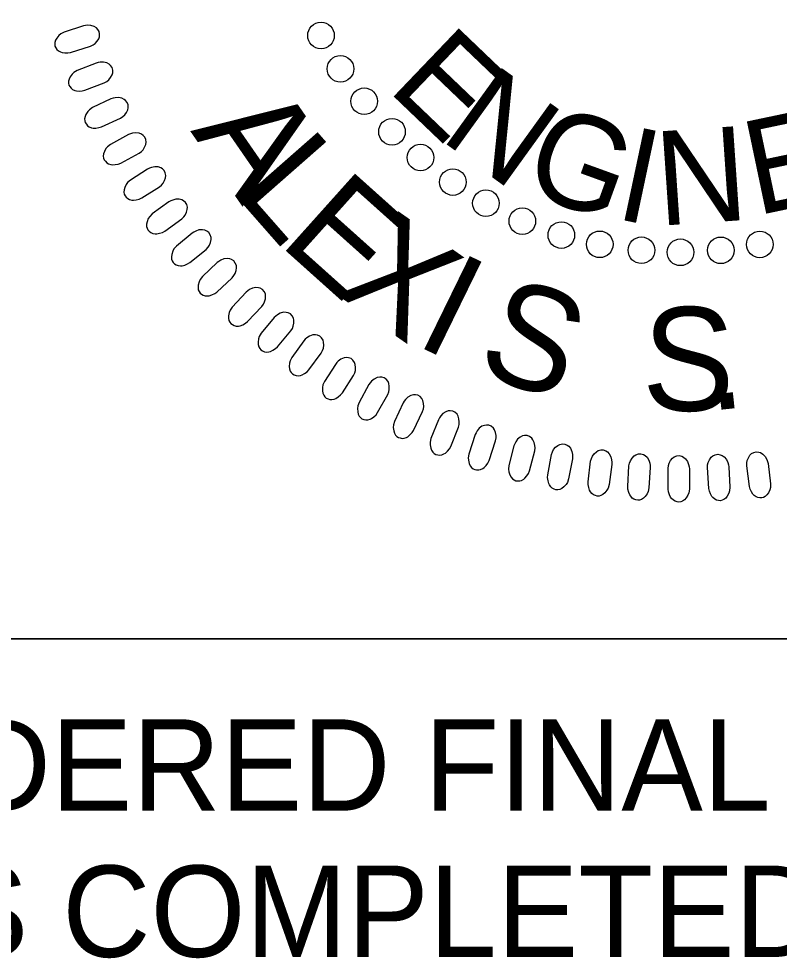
# Model space of a CAD drawing. Extents: x 502400 to 509344, y 448070 to 484209.
# Drawn here: x 507178.9 to 507224.6, y 484026.9 to 484083.5 of the extents above; entities that cross this region are included whole.
import ezdxf

# ---------------------------------------------------------------- set-up
doc = ezdxf.new("R2010")
doc.units = 0
for name, color, linetype in [('Sheet PE Seal Cell', 7, 'Continuous'), ('Sheet Profile CELL', 7, 'Continuous'), ('Sheet Sticker Exception Certification CELL', 7, 'Continuous')]:
    doc.layers.add(name, color=color, linetype=linetype)

msp = doc.modelspace()

# ---------------------------------------------------------------- linework, layer by layer
at = {"layer": 'Sheet PE Seal Cell'}
for points in [[(507182.763, 484083.049), (507181.597, 484082.67), (507181.399, 484082.567), (507181.282, 484082.475), (507181.156, 484082.315), (507181.081, 484082.188), (507181.04, 484082.057), (507181.035, 484081.946), (507181.05, 484081.833), (507181.104, 484081.733), (507181.17, 484081.628), (507181.258, 484081.547), (507181.386, 484081.479), (507181.48, 484081.446), (507181.643, 484081.428), (507181.832, 484081.427), (507181.991, 484081.454), (507183.189, 484081.835), (507183.343, 484081.909), (507183.462, 484081.995), (507183.585, 484082.129), (507183.684, 484082.279), (507183.73, 484082.396), (507183.738, 484082.564), (507183.711, 484082.713), (507183.627, 484082.842), (507183.547, 484082.926), (507183.414, 484083.016), (507183.215, 484083.078), (507183.024, 484083.086), (507182.891, 484083.074)], [(507183.522, 484080.812), (507182.381, 484080.361), (507182.191, 484080.245), (507182.08, 484080.145), (507181.964, 484079.978), (507181.897, 484079.847), (507181.865, 484079.714), (507181.866, 484079.602), (507181.888, 484079.49), (507181.948, 484079.394), (507182.02, 484079.294), (507182.114, 484079.218), (507182.246, 484079.158), (507182.342, 484079.131), (507182.506, 484079.124), (507182.694, 484079.134), (507182.851, 484079.172), (507184.022, 484079.627), (507184.172, 484079.71), (507184.285, 484079.804), (507184.4, 484079.945), (507184.489, 484080.101), (507184.528, 484080.221), (507184.526, 484080.389), (507184.489, 484080.536), (507184.397, 484080.659), (507184.312, 484080.739), (507184.173, 484080.82), (507183.971, 484080.868), (507183.779, 484080.866), (507183.648, 484080.845)], [(507184.422, 484078.652), (507183.311, 484078.13), (507183.129, 484078.003), (507183.024, 484077.896), (507182.919, 484077.722), (507182.861, 484077.588), (507182.837, 484077.452), (507182.845, 484077.341), (507182.875, 484077.231), (507182.941, 484077.138), (507183.019, 484077.043), (507183.117, 484076.973), (507183.252, 484076.921), (507183.349, 484076.901), (507183.513, 484076.904), (507183.702, 484076.926), (507183.855, 484076.973), (507184.996, 484077.501), (507185.14, 484077.594), (507185.247, 484077.694), (507185.353, 484077.842), (507185.432, 484078.004), (507185.463, 484078.126), (507185.45, 484078.293), (507185.404, 484078.437), (507185.305, 484078.555), (507185.215, 484078.629), (507185.071, 484078.702), (507184.867, 484078.737), (507184.675, 484078.722), (507184.545, 484078.694)], [(507185.469, 484076.503), (507184.393, 484075.913), (507184.22, 484075.775), (507184.122, 484075.661), (507184.027, 484075.482), (507183.978, 484075.343), (507183.962, 484075.207), (507183.978, 484075.096), (507184.014, 484074.988), (507184.086, 484074.9), (507184.17, 484074.809), (507184.272, 484074.746), (507184.41, 484074.703), (507184.509, 484074.688), (507184.672, 484074.702), (507184.858, 484074.736), (507185.009, 484074.792), (507186.114, 484075.391), (507186.252, 484075.493), (507186.353, 484075.599), (507186.449, 484075.755), (507186.517, 484075.92), (507186.541, 484076.044), (507186.518, 484076.21), (507186.463, 484076.351), (507186.356, 484076.462), (507186.262, 484076.53), (507186.114, 484076.594), (507185.907, 484076.616), (507185.717, 484076.589), (507185.59, 484076.553)], [(507186.626, 484074.429), (507185.589, 484073.772), (507185.424, 484073.623), (507185.334, 484073.504), (507185.251, 484073.318), (507185.21, 484073.178), (507185.203, 484073.04), (507185.225, 484072.93), (507185.269, 484072.825), (507185.346, 484072.741), (507185.435, 484072.656), (507185.541, 484072.6), (507185.682, 484072.565), (507185.781, 484072.557), (507185.944, 484072.58), (507186.127, 484072.626), (507186.274, 484072.692), (507187.339, 484073.359), (507187.47, 484073.468), (507187.564, 484073.582), (507187.651, 484073.743), (507187.709, 484073.912), (507187.724, 484074.037), (507187.69, 484074.202), (507187.627, 484074.339), (507187.514, 484074.443), (507187.415, 484074.505), (507187.263, 484074.559), (507187.056, 484074.569), (507186.867, 484074.53), (507186.743, 484074.486)], [(507187.902, 484072.454), (507186.909, 484071.733), (507186.754, 484071.574), (507186.67, 484071.45), (507186.6, 484071.259), (507186.568, 484071.116), (507186.57, 484070.978), (507186.599, 484070.871), (507186.648, 484070.767), (507186.73, 484070.689), (507186.825, 484070.61), (507186.935, 484070.56), (507187.077, 484070.534), (507187.177, 484070.533), (507187.337, 484070.566), (507187.518, 484070.623), (507187.66, 484070.698), (507188.681, 484071.431), (507188.805, 484071.549), (507188.892, 484071.667), (507188.968, 484071.833), (507189.015, 484072.006), (507189.023, 484072.132), (507188.979, 484072.294), (507188.907, 484072.427), (507188.787, 484072.524), (507188.685, 484072.579), (507188.53, 484072.624), (507188.323, 484072.621), (507188.137, 484072.57), (507188.015, 484072.518)], [(507189.305, 484070.572), (507188.36, 484069.791), (507188.215, 484069.623), (507188.14, 484069.493), (507188.081, 484069.299), (507188.058, 484069.154), (507188.068, 484069.017), (507188.104, 484068.911), (507188.161, 484068.811), (507188.247, 484068.738), (507188.347, 484068.665), (507188.459, 484068.622), (507188.602, 484068.605), (507188.702, 484068.61), (507188.861, 484068.653), (507189.037, 484068.722), (507189.174, 484068.806), (507190.148, 484069.601), (507190.264, 484069.726), (507190.342, 484069.85), (507190.408, 484070.02), (507190.445, 484070.196), (507190.445, 484070.321), (507190.391, 484070.481), (507190.31, 484070.609), (507190.185, 484070.698), (507190.079, 484070.747), (507189.921, 484070.782), (507189.715, 484070.766), (507189.533, 484070.703), (507189.415, 484070.644)], [(507190.815, 484068.802), (507189.921, 484067.962), (507189.787, 484067.786), (507189.72, 484067.652), (507189.673, 484067.454), (507189.66, 484067.308), (507189.679, 484067.171), (507189.721, 484067.067), (507189.783, 484066.972), (507189.875, 484066.904), (507189.979, 484066.837), (507190.093, 484066.802), (507190.238, 484066.794), (507190.336, 484066.805), (507190.492, 484066.858), (507190.664, 484066.938), (507190.796, 484067.03), (507191.717, 484067.885), (507191.825, 484068.017), (507191.896, 484068.146), (507191.952, 484068.32), (507191.977, 484068.497), (507191.968, 484068.623), (507191.904, 484068.779), (507191.816, 484068.901), (507191.685, 484068.983), (507191.577, 484069.025), (507191.417, 484069.049), (507191.212, 484069.02), (507191.035, 484068.946), (507190.92, 484068.879)], [(507192.551, 484067.024), (507191.711, 484066.13), (507191.588, 484065.944), (507191.53, 484065.807), (507191.496, 484065.606), (507191.491, 484065.459), (507191.518, 484065.325), (507191.567, 484065.225), (507191.636, 484065.133), (507191.731, 484065.071), (507191.839, 484065.011), (507191.956, 484064.982), (507192.1, 484064.984), (507192.198, 484065.001), (507192.35, 484065.063), (507192.516, 484065.154), (507192.642, 484065.254), (507193.508, 484066.165), (507193.608, 484066.304), (507193.671, 484066.437), (507193.715, 484066.614), (507193.728, 484066.792), (507193.712, 484066.917), (507193.639, 484067.068), (507193.543, 484067.186), (507193.407, 484067.259), (507193.297, 484067.294), (507193.136, 484067.309), (507192.933, 484067.267), (507192.76, 484067.182), (507192.65, 484067.108)], [(507194.241, 484065.494), (507193.458, 484064.548), (507193.348, 484064.355), (507193.298, 484064.215), (507193.277, 484064.013), (507193.282, 484063.866), (507193.317, 484063.733), (507193.372, 484063.635), (507193.446, 484063.548), (507193.544, 484063.493), (507193.656, 484063.44), (507193.774, 484063.419), (507193.92, 484063.429), (507194.016, 484063.452), (507194.163, 484063.524), (507194.324, 484063.624), (507194.443, 484063.733), (507195.25, 484064.697), (507195.341, 484064.841), (507195.395, 484064.978), (507195.428, 484065.158), (507195.431, 484065.336), (507195.407, 484065.461), (507195.324, 484065.606), (507195.221, 484065.717), (507195.081, 484065.782), (507194.968, 484065.81), (507194.807, 484065.814), (507194.607, 484065.76), (507194.439, 484065.664), (507194.335, 484065.584)], [(507196.022, 484064.093), (507195.3, 484063.1), (507195.202, 484062.901), (507195.162, 484062.757), (507195.152, 484062.554), (507195.167, 484062.408), (507195.211, 484062.278), (507195.272, 484062.184), (507195.351, 484062.102), (507195.453, 484062.052), (507195.568, 484062.006), (507195.687, 484061.993), (507195.831, 484062.012), (507195.926, 484062.041), (507196.068, 484062.123), (507196.222, 484062.233), (507196.334, 484062.349), (507197.079, 484063.361), (507197.161, 484063.511), (507197.206, 484063.651), (507197.228, 484063.832), (507197.22, 484064.011), (507197.188, 484064.132), (507197.096, 484064.274), (507196.986, 484064.378), (507196.842, 484064.433), (507196.728, 484064.454), (507196.567, 484064.449), (507196.371, 484064.381), (507196.21, 484064.276), (507196.11, 484064.188)], [(507197.924, 484062.68), (507197.266, 484061.644), (507197.18, 484061.439), (507197.149, 484061.293), (507197.152, 484061.089), (507197.176, 484060.945), (507197.228, 484060.818), (507197.294, 484060.727), (507197.379, 484060.651), (507197.484, 484060.608), (507197.601, 484060.568), (507197.721, 484060.563), (507197.863, 484060.591), (507197.957, 484060.627), (507198.094, 484060.716), (507198.24, 484060.836), (507198.345, 484060.959), (507199.024, 484062.016), (507199.096, 484062.171), (507199.133, 484062.313), (507199.143, 484062.496), (507199.124, 484062.673), (507199.084, 484062.793), (507198.984, 484062.928), (507198.868, 484063.024), (507198.72, 484063.071), (507198.605, 484063.085), (507198.445, 484063.07), (507198.253, 484062.99), (507198.1, 484062.874), (507198.005, 484062.781)], [(507199.941, 484061.464), (507199.35, 484060.39), (507199.277, 484060.179), (507199.255, 484060.032), (507199.272, 484059.829), (507199.304, 484059.686), (507199.364, 484059.562), (507199.436, 484059.477), (507199.526, 484059.405), (507199.633, 484059.369), (507199.752, 484059.337), (507199.873, 484059.339), (507200.012, 484059.376), (507200.103, 484059.417), (507200.235, 484059.516), (507200.373, 484059.644), (507200.47, 484059.773), (507201.082, 484060.871), (507201.144, 484061.03), (507201.172, 484061.174), (507201.17, 484061.357), (507201.14, 484061.533), (507201.093, 484061.65), (507200.984, 484061.778), (507200.863, 484061.868), (507200.713, 484061.905), (507200.597, 484061.912), (507200.437, 484061.886), (507200.251, 484061.794), (507200.105, 484061.67), (507200.017, 484061.571)], [(507202.001, 484060.358), (507201.478, 484059.248), (507201.419, 484059.034), (507201.406, 484058.885), (507201.435, 484058.684), (507201.477, 484058.543), (507201.544, 484058.423), (507201.621, 484058.343), (507201.715, 484058.277), (507201.825, 484058.247), (507201.945, 484058.223), (507202.066, 484058.233), (507202.203, 484058.279), (507202.291, 484058.325), (507202.416, 484058.432), (507202.547, 484058.568), (507202.635, 484058.703), (507203.177, 484059.837), (507203.229, 484060), (507203.247, 484060.145), (507203.235, 484060.328), (507203.193, 484060.502), (507203.138, 484060.616), (507203.022, 484060.737), (507202.895, 484060.819), (507202.743, 484060.846), (507202.627, 484060.846), (507202.47, 484060.81), (507202.29, 484060.707), (507202.152, 484060.573), (507202.07, 484060.469)], [(507204.128, 484059.35), (507203.676, 484058.209), (507203.63, 484057.991), (507203.627, 484057.842), (507203.669, 484057.643), (507203.719, 484057.505), (507203.794, 484057.39), (507203.876, 484057.314), (507203.974, 484057.254), (507204.085, 484057.232), (507204.207, 484057.216), (507204.326, 484057.232), (507204.46, 484057.287), (507204.546, 484057.339), (507204.663, 484057.453), (507204.785, 484057.598), (507204.865, 484057.738), (507205.334, 484058.904), (507205.376, 484059.069), (507205.385, 484059.216), (507205.361, 484059.397), (507205.309, 484059.568), (507205.247, 484059.678), (507205.124, 484059.792), (507204.991, 484059.865), (507204.838, 484059.883), (507204.722, 484059.875), (507204.568, 484059.83), (507204.394, 484059.716), (507204.265, 484059.573), (507204.19, 484059.464)], [(507206.337, 484058.448), (507205.957, 484057.281), (507205.925, 484057.06), (507205.931, 484056.912), (507205.986, 484056.716), (507206.044, 484056.581), (507206.127, 484056.471), (507206.213, 484056.401), (507206.314, 484056.347), (507206.427, 484056.331), (507206.55, 484056.323), (507206.668, 484056.347), (507206.798, 484056.41), (507206.88, 484056.467), (507206.99, 484056.589), (507207.102, 484056.741), (507207.173, 484056.885), (507207.569, 484058.078), (507207.6, 484058.247), (507207.6, 484058.393), (507207.564, 484058.572), (507207.501, 484058.74), (507207.433, 484058.846), (507207.303, 484058.951), (507207.166, 484059.017), (507207.012, 484059.025), (507206.897, 484059.009), (507206.745, 484058.954), (507206.58, 484058.83), (507206.46, 484058.68), (507206.391, 484058.566)], [(507208.67, 484057.774), (507208.364, 484056.586), (507208.346, 484056.365), (507208.361, 484056.217), (507208.428, 484056.024), (507208.495, 484055.894), (507208.584, 484055.789), (507208.675, 484055.724), (507208.779, 484055.677), (507208.892, 484055.669), (507209.016, 484055.668), (507209.132, 484055.699), (507209.258, 484055.77), (507209.336, 484055.831), (507209.438, 484055.96), (507209.541, 484056.119), (507209.602, 484056.268), (507209.923, 484057.483), (507209.943, 484057.653), (507209.934, 484057.8), (507209.887, 484057.976), (507209.813, 484058.14), (507209.739, 484058.241), (507209.601, 484058.338), (507209.462, 484058.394), (507209.307, 484058.393), (507209.193, 484058.371), (507209.045, 484058.306), (507208.888, 484058.171), (507208.777, 484058.014), (507208.717, 484057.896)], [(507212.192, 484056.987), (507211.961, 484055.782), (507211.884, 484055.574), (507211.806, 484055.446), (507211.664, 484055.3), (507211.548, 484055.211), (507211.423, 484055.154), (507211.313, 484055.134), (507211.199, 484055.136), (507211.093, 484055.176), (507210.981, 484055.228), (507210.889, 484055.306), (507210.805, 484055.424), (507210.761, 484055.514), (507210.723, 484055.673), (507210.698, 484055.861), (507210.706, 484056.022), (507210.935, 484057.257), (507210.989, 484057.42), (507211.059, 484057.548), (507211.177, 484057.688), (507211.313, 484057.804), (507211.424, 484057.865), (507211.589, 484057.894), (507211.74, 484057.885), (507211.879, 484057.818), (507211.973, 484057.749), (507212.079, 484057.628), (507212.164, 484057.439), (507212.197, 484057.25), (507212.201, 484057.117)], [(507214.558, 484056.661), (507214.404, 484055.444), (507214.339, 484055.231), (507214.27, 484055.099), (507214.137, 484054.944), (507214.027, 484054.848), (507213.906, 484054.782), (507213.797, 484054.756), (507213.683, 484054.751), (507213.575, 484054.785), (507213.459, 484054.829), (507213.363, 484054.901), (507213.273, 484055.014), (507213.223, 484055.101), (507213.175, 484055.258), (507213.138, 484055.443), (507213.136, 484055.604), (507213.286, 484056.851), (507213.33, 484057.017), (507213.392, 484057.15), (507213.501, 484057.297), (507213.63, 484057.422), (507213.736, 484057.488), (507213.899, 484057.528), (507214.05, 484057.529), (507214.193, 484057.471), (507214.291, 484057.408), (507214.405, 484057.293), (507214.501, 484057.11), (507214.546, 484056.923), (507214.559, 484056.791)], [(507216.875, 484056.463), (507216.797, 484055.239), (507216.747, 484055.023), (507216.686, 484054.886), (507216.563, 484054.724), (507216.459, 484054.62), (507216.342, 484054.548), (507216.235, 484054.515), (507216.121, 484054.502), (507216.012, 484054.53), (507215.894, 484054.566), (507215.794, 484054.633), (507215.695, 484054.739), (507215.64, 484054.822), (507215.583, 484054.976), (507215.534, 484055.159), (507215.522, 484055.32), (507215.594, 484056.574), (507215.627, 484056.742), (507215.681, 484056.878), (507215.781, 484057.032), (507215.901, 484057.165), (507216.003, 484057.238), (507216.163, 484057.288), (507216.314, 484057.298), (507216.461, 484057.248), (507216.561, 484057.192), (507216.682, 484057.085), (507216.791, 484056.908), (507216.847, 484056.724), (507216.868, 484056.594)], [(507219.229, 484056.392), (507219.228, 484055.164), (507219.19, 484054.946), (507219.138, 484054.806), (507219.026, 484054.636), (507218.929, 484054.526), (507218.816, 484054.446), (507218.712, 484054.407), (507218.6, 484054.387), (507218.488, 484054.407), (507218.368, 484054.437), (507218.263, 484054.496), (507218.159, 484054.597), (507218.099, 484054.677), (507218.032, 484054.826), (507217.972, 484055.006), (507217.95, 484055.165), (507217.943, 484056.421), (507217.965, 484056.591), (507218.01, 484056.731), (507218.1, 484056.89), (507218.212, 484057.03), (507218.31, 484057.11), (507218.466, 484057.169), (507218.616, 484057.189), (507218.765, 484057.149), (507218.87, 484057.099), (507218.998, 484057), (507219.116, 484056.83), (507219.184, 484056.65), (507219.213, 484056.521)], [(507221.596, 484056.514), (507221.672, 484055.289), (507221.649, 484055.068), (507221.606, 484054.926), (507221.504, 484054.749), (507221.414, 484054.633), (507221.307, 484054.547), (507221.205, 484054.501), (507221.094, 484054.474), (507220.982, 484054.487), (507220.86, 484054.51), (507220.752, 484054.562), (507220.641, 484054.656), (507220.576, 484054.731), (507220.5, 484054.877), (507220.429, 484055.052), (507220.397, 484055.21), (507220.31, 484056.463), (507220.322, 484056.634), (507220.359, 484056.776), (507220.439, 484056.941), (507220.541, 484057.087), (507220.634, 484057.173), (507220.786, 484057.243), (507220.935, 484057.272), (507221.086, 484057.241), (507221.193, 484057.198), (507221.327, 484057.107), (507221.456, 484056.945), (507221.535, 484056.77), (507221.573, 484056.642)], [(507223.961, 484056.708), (507224.114, 484055.491), (507224.105, 484055.268), (507224.071, 484055.123), (507223.981, 484054.941), (507223.898, 484054.82), (507223.796, 484054.726), (507223.698, 484054.674), (507223.589, 484054.64), (507223.475, 484054.646), (507223.353, 484054.661), (507223.242, 484054.707), (507223.125, 484054.793), (507223.056, 484054.865), (507222.97, 484055.005), (507222.888, 484055.175), (507222.846, 484055.331), (507222.682, 484056.577), (507222.683, 484056.747), (507222.71, 484056.892), (507222.779, 484057.061), (507222.872, 484057.213), (507222.959, 484057.305), (507223.107, 484057.384), (507223.254, 484057.423), (507223.407, 484057.401), (507223.517, 484057.365), (507223.655, 484057.282), (507223.794, 484057.129), (507223.884, 484056.959), (507223.93, 484056.835)]]:
    msp.add_lwpolyline(points, close=True, dxfattribs=at)
for centre in [(507197.061, 484082.469), (507198.23, 484080.465), (507199.663, 484078.513), (507201.334, 484076.679), (507203.046, 484075.125), (507204.996, 484073.651), (507206.986, 484072.375), (507209.176, 484071.299), (507211.524, 484070.462), (507213.833, 484069.903), (507223.468, 484069.9), (507216.341, 484069.544), (507218.69, 484069.423), (507221.119, 484069.542)]:
    msp.add_circle(centre, 0.801, dxfattribs=at)
at = {"layer": 'Sheet Profile CELL'}
msp.add_lwpolyline([(507169.08, 484158.662), (507269.08, 484158.662), (507269.08, 484046.162), (507169.08, 484046.162)], close=True, dxfattribs=at)
at = {"layer": 'Sheet Sticker Exception Certification CELL'}
msp.add_line((507069.03, 484046.162), (507269.067, 484046.162), dxfattribs=at)
msp.add_line((507069.03, 484046.162), (507269.067, 484046.162), dxfattribs=at)

# ---------------------------------------------------------------- texts
at = {"layer": 'Sheet PE Seal Cell'}
for s, height, rotation, p in [('E', 5.669, 316.2656, (507200.984, 484079.231)), ('N', 5.669, 324.2054, (507204.119, 484076.275)), ('A', 6.236, 304.6834, (507189.182, 484076.729)), ('G', 5.669, 340.085, (507209.013, 484073.177)), ('E', 5.669, 11.8442, (507223.243, 484071.621)), ('I', 5.669, 348.0248, (507214.641, 484071.487)), ('N', 5.669, 3.9044, (507217.395, 484071.015)), ('L', 6.236, 311.3031, (507191.722, 484073.049)), ('E', 6.236, 318.1488, (507194.435, 484069.967)), ('X', 6.236, 324.9944, (507197.836, 484066.994)), ('I', 6.236, 333.9418, (507202.585, 484063.934)), ('S', 6.236, 340.7874, (507206.241, 484062.24)), ('S', 6.236, 359.3826, (507216.362, 484059.918)), ('.', 6.236, 6.2283, (507220.401, 484059.869))]:
    msp.add_text(s, height=height, rotation=rotation, dxfattribs=at).set_placement(p)
at = {"layer": 'Sheet Sticker Exception Certification CELL'}
for s, p in [('DOCUMENT NOT CONSIDERED FINAL', (507090.101, 484035.816)), ('DOCUMENT NOT CONSIDERED FINAL', (507090.101, 484035.816)), ('UNLESS ALL SIGNATURES COMPLETED', (507085.03, 484027.016)), ('UNLESS ALL SIGNATURES COMPLETED', (507085.03, 484027.016))]:
    msp.add_text(s, height=5.5, dxfattribs=at).set_placement(p)

doc.saveas('drawing.dxf')
